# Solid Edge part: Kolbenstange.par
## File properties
Username: bmolnar
Dokumentum tartalom típus: 0
Author: bmolnar
Last saved by: bmolnar
Revision: 79
Sűrűség: 0,000 kg/m^3
Pontosság: 0,990
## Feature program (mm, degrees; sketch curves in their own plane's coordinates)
base feature "unnamed BaseFeature 1"
sketch for "unnamed Protrusion 1" plane through (57, 0, 0) normal (1, 0, 0) x-axis (0, -1, 0)
  circle centre (0, 0) radius 40
extrude "unnamed Protrusion 1" add finite 12 along +normal
thread "unnamed Thread 1"
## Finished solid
Body 1: solid body, 17 faces, 23 edges, 8 vertices.
  Faces by surface: plane 8, cylinder 4, torus 3, cone 2
  Edges by curve: circle 13, line 6, ellipse 2, intersection 2
Bounding box of the edges (mm; curved faces can reach further): 79.000 x 80.000 x 80.000, from (-10, -40, -40) to (69, 40, 40).
Cylindrical faces by radius (mm): R6.75 x1, R8 x1, R10 x1, R40 x1
Conical faces (half-angle, radius in mm at the cone's reference point): 20 deg R7.4 x1, 60 deg R7.475 x1
Toroidal faces (ring radius, tube radius in mm): R7.15 r0.4 x2, R8.2 r1.8 x1
Planar faces by outward normal: +x 1, +y 1, -x 3, -y 1, oblique 2
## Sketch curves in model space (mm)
circle centre (57, 0, 0) radius 40
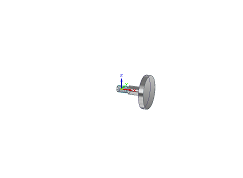
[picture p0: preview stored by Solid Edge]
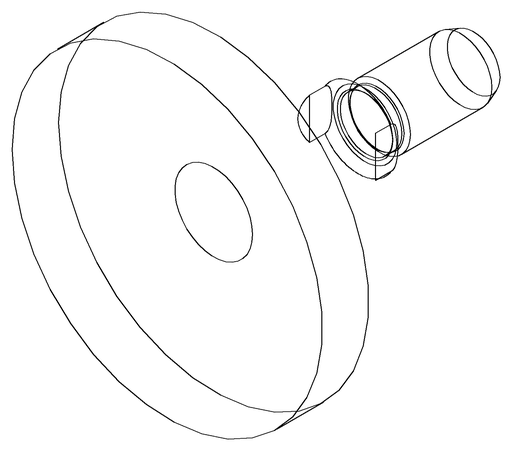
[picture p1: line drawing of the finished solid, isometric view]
